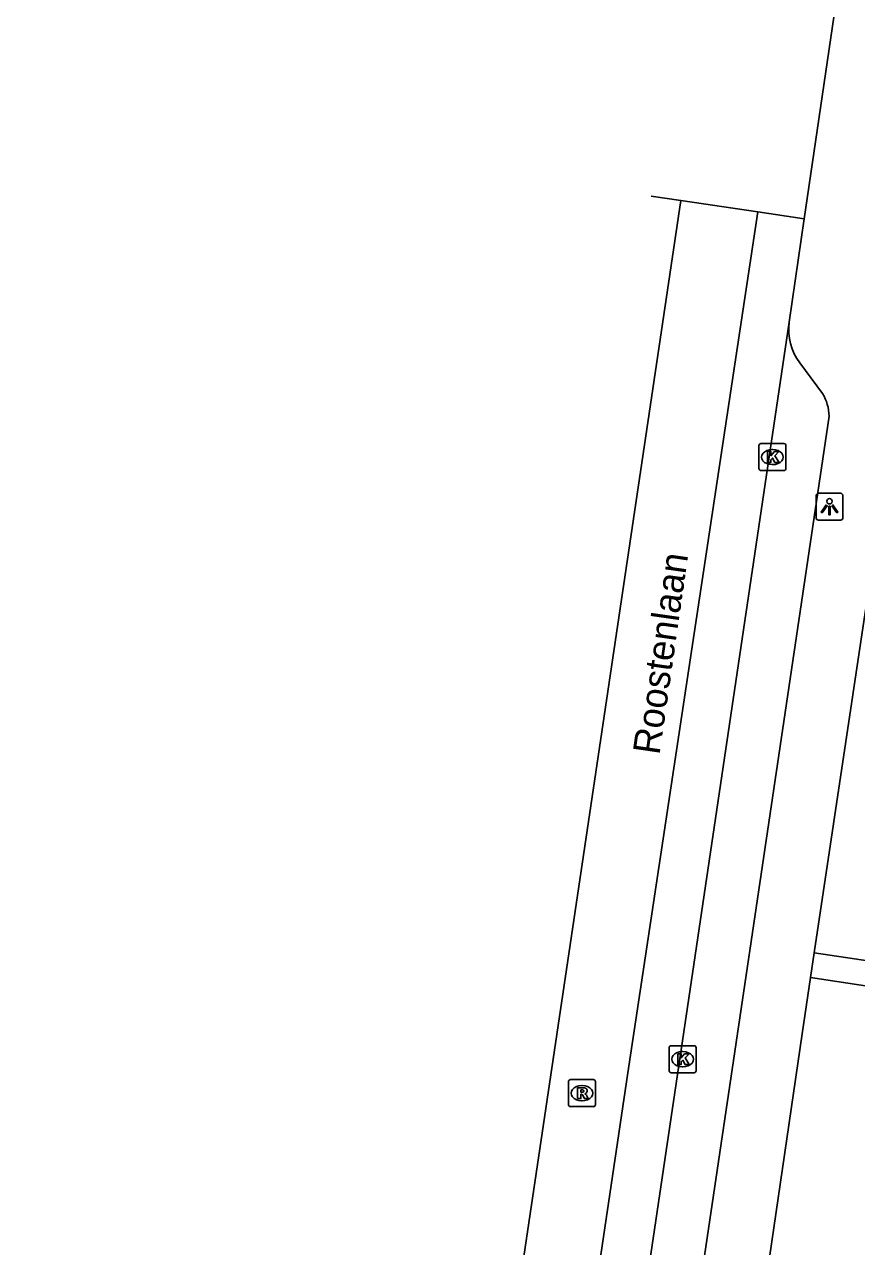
# Model space of a CAD drawing. Extents: x 162250 to 162654, y 380744 to 381605.
# Drawn here: x 162321.67 to 162352.5, y 381503.98 to 381549.25 of the extents above; entities that cross this region are included whole.
import ezdxf

# ---------------------------------------------------------------- set-up
doc = ezdxf.new("R2010")
doc.units = 0
for name, color, linetype in [('IMGEO_Kolk', 7, 'Continuous'), ('IMGEO_Lichtpunt', 7, 'Continuous'), ('IMGEO_Openbare_ruimte_label', 7, 'Continuous'), ('IMGEO_Rijbaan_lokaal_gesloten', 7, 'Continuous'), ('IMGEO_Rijbaan_lokaal_open', 7, 'Continuous'), ('IMGEO_Rioolput', 7, 'Continuous'), ('IMGEO_Voetpad_open', 7, 'Continuous')]:
    doc.layers.add(name, color=color, linetype=linetype)

msp = doc.modelspace()

# ---------------------------------------------------------------- linework, layer by layer
at = {"layer": 'IMGEO_Kolk'}
for p, q in [((162348.881, 381532.797), (162348.881, 381533.649)), ((162348.956, 381533.723), (162349.808, 381533.723)), ((162349.882, 381533.649), (162349.882, 381532.797)), ((162349.369, 381533.503), (162349.394, 381533.503)), ((162349.392, 381532.943), (162349.367, 381532.943)), ((162349.808, 381532.723), (162348.956, 381532.723)), ((162345.555, 381510.493), (162345.555, 381511.345)), ((162345.63, 381511.419), (162346.482, 381511.419)), ((162346.043, 381511.199), (162346.068, 381511.199)), ((162346.556, 381511.345), (162346.556, 381510.493)), ((162346.066, 381510.639), (162346.041, 381510.639)), ((162346.482, 381510.419), (162345.63, 381510.419))]:
    msp.add_line(p, q, dxfattribs=at)
for points in [[(162348.881, 381532.797), (162348.881, 381533.649)], [(162348.956, 381533.723), (162349.808, 381533.723)], [(162349.882, 381533.649), (162349.882, 381532.797)], [(162349.202, 381533.423), (162349.325, 381533.423), (162349.325, 381533.272), (162349.455, 381533.423), (162349.619, 381533.423), (162349.473, 381533.272), (162349.626, 381533.023), (162349.474, 381533.023), (162349.389, 381533.187), (162349.325, 381533.12), (162349.325, 381533.023), (162349.202, 381533.023), (162349.202, 381533.423)], [(162349.808, 381532.723), (162348.956, 381532.723)], [(162345.555, 381510.493), (162345.555, 381511.345)], [(162345.63, 381511.419), (162346.482, 381511.419)], [(162345.876, 381511.119), (162345.999, 381511.119), (162345.999, 381510.968), (162346.129, 381511.119), (162346.293, 381511.119), (162346.147, 381510.968), (162346.3, 381510.719), (162346.148, 381510.719), (162346.063, 381510.883), (162345.999, 381510.816), (162345.999, 381510.719), (162345.876, 381510.719), (162345.876, 381511.119)], [(162346.556, 381511.345), (162346.556, 381510.493)], [(162346.482, 381510.419), (162345.63, 381510.419)]]:
    msp.add_lwpolyline(points, dxfattribs=at)
for centre, start, end in [((162348.958, 381533.647), 91.552, 178.448), ((162348.958, 381533.647), 91.552, 178.448), ((162349.806, 381533.647), 1.552, 88.448), ((162349.806, 381533.647), 1.552, 88.448), ((162348.958, 381532.799), 181.552, 268.448), ((162348.958, 381532.799), 181.552, 268.448), ((162349.806, 381532.799), 271.552, 358.448), ((162349.806, 381532.799), 271.552, 358.448), ((162345.632, 381511.343), 91.552, 178.448), ((162345.632, 381511.343), 91.552, 178.448), ((162346.48, 381511.343), 1.552, 88.448), ((162346.48, 381511.343), 1.552, 88.448), ((162345.632, 381510.495), 181.552, 268.448), ((162345.632, 381510.495), 181.552, 268.448), ((162346.48, 381510.495), 271.552, 358.448), ((162346.48, 381510.495), 271.552, 358.448)]:
    msp.add_arc(centre, 0.0765, start, end, dxfattribs=at)
for centre, major_axis, ratio, start_param, end_param in [((162349.368, 381533.223), (-0.387, 0.002), 0.722429, 4.712389, 7.853982), ((162349.393, 381533.223), (-0.39, 0.002), 0.717154, 1.570796, 4.712389), ((162346.042, 381510.919), (-0.387, 0.002), 0.722429, 4.712389, 7.853982), ((162346.067, 381510.919), (-0.39, 0.002), 0.717154, 1.570796, 4.712389)]:
    msp.add_ellipse(centre, major_axis=major_axis, ratio=ratio, start_param=start_param, end_param=end_param, dxfattribs=at)
at = {"layer": 'IMGEO_Lichtpunt'}
for p, q in [((162351.899, 381531.881), (162351.091, 381531.881)), ((162351.899, 381531.881), (162351.091, 381531.881)), ((162350.997, 381531.786), (162350.997, 381530.979)), ((162350.997, 381531.786), (162350.997, 381530.979)), ((162351.993, 381530.979), (162351.993, 381531.786)), ((162351.993, 381530.979), (162351.993, 381531.786)), ((162351.091, 381530.885), (162351.899, 381530.885)), ((162351.091, 381530.885), (162351.899, 381530.885))]:
    msp.add_line(p, q, dxfattribs=at)
for points in [[(162351.371, 381531.45), (162351.41, 381531.422), (162351.222, 381531.16), (162351.184, 381531.187), (162351.371, 381531.45)], [(162351.473, 381531.402), (162351.52, 381531.402), (162351.52, 381531.08), (162351.473, 381531.08), (162351.473, 381531.402)], [(162351.583, 381531.422), (162351.621, 381531.449), (162351.808, 381531.187), (162351.769, 381531.159), (162351.583, 381531.422)]]:
    msp.add_lwpolyline(points, dxfattribs=at)
msp.add_circle((162351.496, 381531.584), 0.0994, dxfattribs=at)
for centre, start, end in [((162351.091, 381531.786), 90, 180), ((162351.091, 381531.786), 90, 180), ((162351.899, 381531.786), 0, 90), ((162351.899, 381531.786), 0, 90), ((162351.091, 381530.979), 180, 270), ((162351.091, 381530.979), 180, 270), ((162351.899, 381530.979), 270, 0), ((162351.899, 381530.979), 270, 360)]:
    msp.add_arc(centre, 0.0946, start, end, dxfattribs=at)
at = {"layer": 'IMGEO_Rijbaan_lokaal_gesloten'}
for points in [[(162321.673, 381379.215), (162345.986, 381542.729)], [(162348.846, 381542.303), (162344.03, 381510.414), (162324.497, 381378.848)], [(162350.562, 381542.047), (162349.998, 381538.218)], [(162343.13, 381491.968), (162349.998, 381538.218)]]:
    msp.add_lwpolyline(points, dxfattribs=at)
at = {"layer": 'IMGEO_Rijbaan_lokaal_open'}
for points in [[(162350.562, 381542.047), (162351.66, 381549.516)], [(162345.986, 381542.729), (162344.886, 381542.888)], [(162345.986, 381542.729), (162348.846, 381542.303)], [(162348.846, 381542.303), (162350.562, 381542.047)]]:
    msp.add_lwpolyline(points, dxfattribs=at)
at = {"layer": 'IMGEO_Rioolput'}
for p, q in [((162341.901, 381510.161), (162342.753, 381510.161)), ((162341.826, 381509.235), (162341.826, 381510.087)), ((162342.314, 381509.941), (162342.339, 381509.941)), ((162342.827, 381510.087), (162342.827, 381509.235)), ((162342.337, 381509.381), (162342.312, 381509.381)), ((162342.753, 381509.161), (162341.901, 381509.161))]:
    msp.add_line(p, q, dxfattribs=at)
for points in [[(162341.901, 381510.161), (162342.753, 381510.161)], [(162341.826, 381509.235), (162341.826, 381510.087)], [(162342.415, 381509.859), (162342.163, 381509.861), (162342.163, 381509.461)], [(162342.341, 381509.78), (162342.287, 381509.78), (162342.287, 381509.699)], [(162342.287, 381509.699), (162342.339, 381509.699)], [(162342.827, 381510.087), (162342.827, 381509.235)], [(162342.163, 381509.461), (162342.287, 381509.461), (162342.287, 381509.623), (162342.298, 381509.623)], [(162342.345, 381509.594), (162342.416, 381509.461), (162342.556, 381509.461), (162342.491, 381509.587)], [(162342.753, 381509.161), (162341.901, 381509.161)]]:
    msp.add_lwpolyline(points, dxfattribs=at)
for centre, radius, start, end in [((162341.903, 381510.085), 0.0765, 91.552, 178.448), ((162341.903, 381510.085), 0.0765, 91.552, 178.448), ((162342.751, 381510.085), 0.0765, 1.552, 88.448), ((162342.751, 381510.085), 0.0765, 1.552, 88.448), ((162342.323, 381509.888), 0.19, 274.7715, 282.9687), ((162342.347, 381509.684), 0.0964, 77.0061, 93.1865), ((162342.361, 381509.741), 0.0378, 276.6634, 79.6772), ((162342.414, 381509.749), 0.109, 350.3612, 89.416), ((162342.412, 381509.749), 0.112, 277.5842, 350.9817), ((162341.903, 381509.237), 0.0765, 181.552, 268.448), ((162341.903, 381509.237), 0.0765, 181.552, 268.448), ((162342.297, 381509.57), 0.0533, 26.0293, 88.6989), ((162342.396, 381509.534), 0.108, 29.5134, 73.7905), ((162342.751, 381509.237), 0.0765, 271.552, 358.448), ((162342.751, 381509.237), 0.0765, 271.552, 358.448)]:
    msp.add_arc(centre, radius, start, end, dxfattribs=at)
for centre, major_axis, ratio, start_param, end_param in [((162342.313, 381509.661), (-0.387, 0.002), 0.722429, 4.712389, 7.853982), ((162342.338, 381509.661), (-0.39, 0.002), 0.717154, 1.570796, 4.712389)]:
    msp.add_ellipse(centre, major_axis=major_axis, ratio=ratio, start_param=start_param, end_param=end_param, dxfattribs=at)
at = {"layer": 'IMGEO_Voetpad_open'}
for points in [[(162371.772, 381588.094), (162370.283, 381588.375), (162363.369, 381585.251), (162361.6, 381584.081), (162363.286, 381580.314), (162362.669, 381579.584), (162359.448, 381578.123), (162359.403, 381573.306), (162358.055, 381562.41), (162350.929, 381514.861)], [(162350.4, 381536.709), (162351.24, 381535.578)], [(162351.478, 381534.742), (162345.57, 381494.908)], [(162350.791, 381513.94), (162350.929, 381514.861)], [(162350.929, 381514.861), (162355.072, 381514.24)], [(162345.951, 381480.835), (162350.479, 381511.856), (162350.791, 381513.94)], [(162350.791, 381513.94), (162354.936, 381513.318)]]:
    msp.add_lwpolyline(points, dxfattribs=at)
for centre, radius, start, end in [((162352.077, 381537.964), 2.094, 173.0282, 216.8063), ((162349.801, 381534.716), 1.677, 0.8751, 30.9071)]:
    msp.add_arc(centre, radius, start, end, dxfattribs=at)

# ---------------------------------------------------------------- texts
at = {"layer": 'IMGEO_Openbare_ruimte_label'}
msp.add_text('Roostenlaan', height=1, rotation=81.8375, dxfattribs=at).set_placement((162345.196, 381522.167))

doc.saveas('drawing.dxf')
